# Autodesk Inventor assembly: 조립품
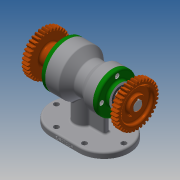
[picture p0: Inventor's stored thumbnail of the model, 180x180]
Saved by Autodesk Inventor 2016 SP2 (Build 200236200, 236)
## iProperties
Created: 2020-01
Part Number: 조립품
Document SubType Name: Assembly
Designer: EZ
Author: EZ
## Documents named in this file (13)
- C:\Users\EZ\Desktop\700104V1027\조립품.iam
- C:\Users\EZ\Desktop\700104V1027\뒤커버.ipt
- C:\Users\EZ\Desktop\700104V1027\멈춤나사 M3.ipt
- C:\Users\EZ\Desktop\700104V1027\베어링 6203.ipt
- C:\Users\EZ\Desktop\700104V1027\베어링 6205.ipt
- C:\Users\EZ\Desktop\700104V1027\본체.ipt
- C:\Users\EZ\Desktop\700104V1027\볼트 M4.ipt
- C:\Users\EZ\Desktop\700104V1027\스퍼기어.ipt
- C:\Users\EZ\Desktop\700104V1027\앞커버.ipt
- C:\Users\EZ\Desktop\700104V1027\오일 실 17 30 8.ipt
- C:\Users\EZ\Desktop\700104V1027\오일 실 25 38 8.ipt
- C:\Users\EZ\Desktop\700104V1027\축.ipt
- C:\Users\EZ\Desktop\700104V1027\키 5 x 5 x 18.ipt
